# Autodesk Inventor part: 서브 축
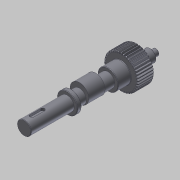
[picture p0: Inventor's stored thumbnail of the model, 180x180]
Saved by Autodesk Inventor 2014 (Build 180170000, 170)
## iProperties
Created: 2016-02
Part Number: 서브 축
Material: 강철, 연강
Document SubType Name: Modeling
Designer: mdu
Categories: <?xml version="1.0" encoding="UTF-16"?> <MemberInstance><Categories><FamilyTemplate><FamilyTemplateParameter ValueType="xs:double" Id="1" ObjectReferenceKey="da
Density: 7.86 g/cm^3
Mass: 504.239 g
Surface Area: 165.256 cm^2
Volume: 64.1526 cm^3
Appearance: 강철
CustomPartVersion: 1
Author: mdu
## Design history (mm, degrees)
sketch "Sketch1"
  geometry: C1 r 21 at (0, 0)
  constraints: 1 centre point
  dimensions: "d0" = 42 diameter of C1 (= da_da)
extrude "Extrusion1" new body sketch "Sketch1" distance "d1" = 20 (= da_b); taper "d2" = 0 deg
workplane "Work Plane2"
feature "피치 지름" dims "d4" = 10, "d5" = 0
workplane "Work Plane8"
workplane "Work Plane9"
chamfer "모따기1" distance "d49" = 1; stored, may be unused: second distance "d50" = 2, angle "d51" = 45 deg
sketch "스케치3"
  geometry: C1 r 12.5 at (0, 0); 1 further point
  constraints: 1 centre point, 1 coincident
  dimensions: "d52" = 25 diameter of C1
extrude "돌출2" join sketch "스케치3" distance "d53" = 16; taper "d54" = 0 deg
sketch "스케치4"
  geometry: C1 r 8.5 at (0, 0); 1 further point
  constraints: 1 centre point, 1 coincident
  dimensions: "d55" = 17 diameter of C1
extrude "돌출3" join sketch "스케치4" distance "d56" = 103; taper "d57" = 0 deg
sketch "스케치5"
  geometry: C1 r 7.5 at (0, 0); 1 further point
  constraints: 1 centre point, 1 coincident
  dimensions: "d62" = 15 diameter of C1
extrude "돌출4" join sketch "스케치5" distance "d63" = 16; taper "d64" = 0 deg
sketch "스케치6"
  geometry: C1 r 4 at (0, 0); 1 further point
  constraints: 1 centre point, 1 coincident
  dimensions: "d65" = 8 diameter of C1
extrude "돌출5" join sketch "스케치6" distance "d66" = 7; taper "d67" = 0 deg
chamfer "모따기2" distance "d58" = 0.5; stored, may be unused: second distance "d59" = 2, angle "d60" = 45 deg
fillet "모깎기1" dims "d61" = 0.5
feature "스퍼 기어" dims "da_b" = 20, "da_d" = 40, "da_aw" = 31, "da_da" = 42, "da_df" = 37.5, "da_dw" = 40, angle "da_beta" = 0 deg, "da_lefttooth" = 0, "da_righttooth" = 0
node "작업 평면11"
sketch "스케치7"
  geometry: C1 r 8.5 at (0, 0) reference; C2 r 11.5 at (0, 3); 1 further point
  constraints: 1 centre point, 1 tangent, 1 vertical alignment
  dimensions: "d71" = 3 distance of C2.centre point (0, 0); "d72" = 23 diameter of C2 (derived)
extrude "돌출6" join sketch "스케치7" stored distance "d73" = 20; taper "d74" = 0 deg
node "작업 평면12"
sketch "스케치8"
  geometry: C1 r 12.5 at (0, 0) reference; 1 further point
extrude "돌출7" join sketch "스케치8" distance "d76" = 5; taper "d77" = 0 deg
chamfer "모따기3" distance "d78" = 0.5; stored, may be unused: second distance "d79" = 2, angle "d80" = 45 deg
sketch "스케치9"
  geometry: L1 (-8.5, 86)-(-8.5, 138.5) reference; L2 (-8, 139)-(8, 139) reference; L3 (0, 0)-(0, 139); L4 (-8.5, 115)-(0, 115); L5 (-8.5, 115)-(-8.5, 113.5); L6 (-7, 115)-(-8.5, 113.5)
  constraints: 8 end point, 4 point on line, 1 midpoint, 1 perpendicular
  dimensions: "d81" = 24 distance between parallel lines of L2 L4; "d82" = 45 deg angle of L6 L5; "d83" = 3 diameter of L5.end L4
revolve "회전1" sketch "스케치9" stored, may be unused: angle "d84" = 90 deg
sketch "스케치10"
  geometry: L1 (-8.5, 113.5)-(-7, 115) reference; L2 (-8.5, 116.5)-(-7, 115) reference; 2 further points
  constraints: 1 coincident
node "작업점1"
node "작업 평면14"
sketch "스케치11"
  geometry: L1 (8.5, 102.5)-(-8.5, 102.5) reference; L2 (0, 102.5)-(0, -36); L3 (-2.5, 93.5)-(-2.5, 80.5); L4 (2.5, 80.5)-(2.5, 93.5); L5 (-8, 103)-(8, 103) reference; A1 r 2.5 centre (0, 93.5) between (2.5, 93.5) and (-2.5, 93.5); A2 r 2.5 centre (0, 80.5) between (-2.5, 80.5) and (2.5, 80.5)
  constraints: 6 end point, 4 point on circle, 4 tangent, 2 centre point, 1 midpoint, 1 parallel, 1 perpendicular, 1 point on line, 1 vertical alignment
  dimensions: "d85" = 7 distance edge to line of A1 L5; "d86" = 18 dimension on A2 A1; "d87" = 5 distance between parallel lines of L3 L4
extrude "돌출8" cut sketch "스케치11" distance "d88" = 3; taper "d89" = 0 deg
body "Solid1"
sketch "Sketch2"
  geometry: C1 r 21 at (0, 0) reference; C2 r 20 at (0, 0)
  constraints: 1 centre point, 1 coincident
  dimensions: "d3" = 40 diameter of C2 (= da_dw)
body "Srf1"
other parameters: "d16" = 31 (= da_aw), "d17" = 0, "d34" = 4.5 deg (computed from da_z), "d39" = 0, "d41" = 0, "d43" = 31 (= da_aw), "d46" = 31 (= da_aw), "d47" = 0, "d48" = 0, "d68" = 25
